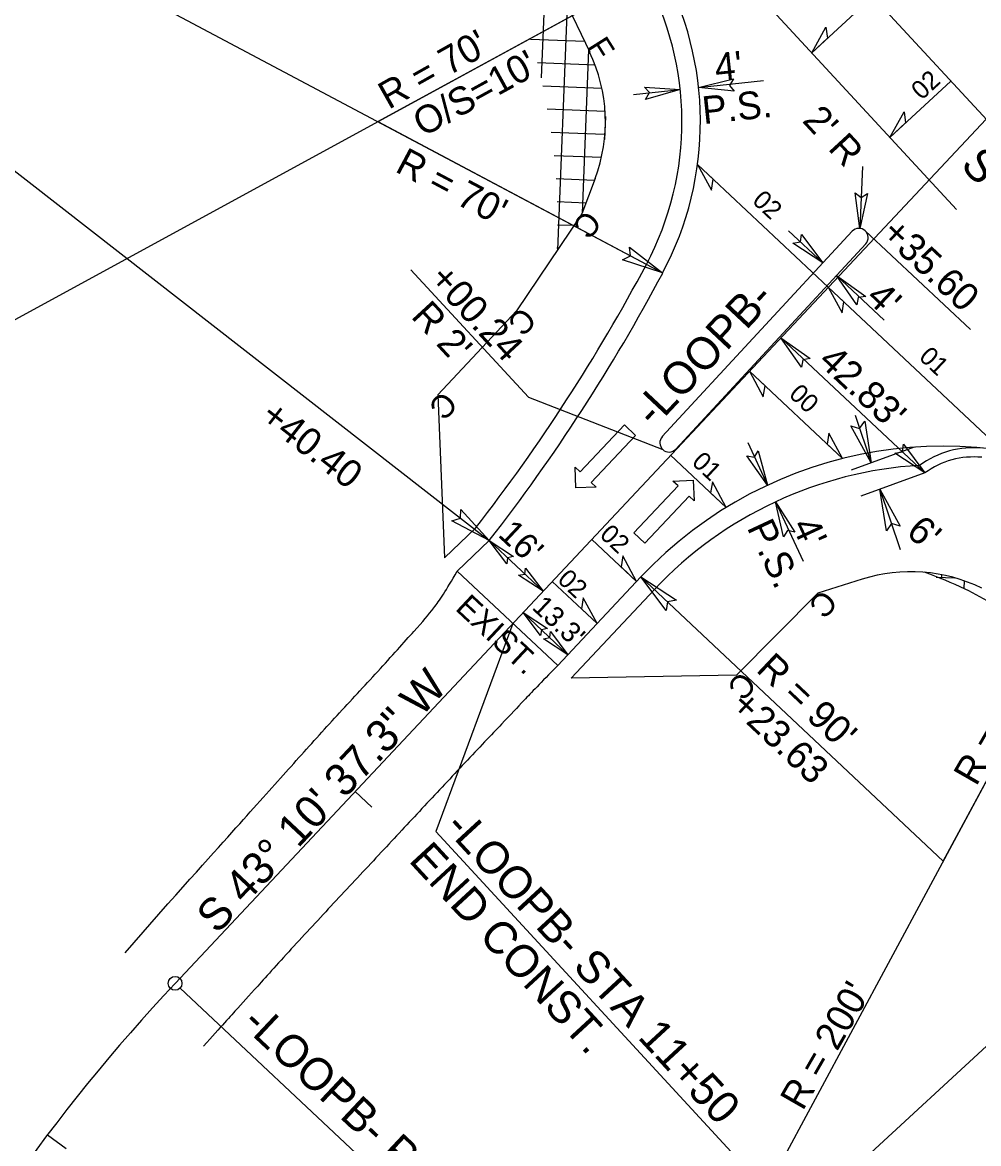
# Model space of a CAD drawing. Extents: x 1702862 to 1704514, y 793768 to 796215.
# Drawn here: x 1703124.4 to 1703331.8, y 795003.7 to 795246.9 of the extents above; entities that cross this region are included whole.
import ezdxf

# ---------------------------------------------------------------- set-up
doc = ezdxf.new("R2010")
doc.units = 0
for name, color, linetype in [('Old_Level_3', 7, 'Continuous'), ('Prop Conc 2ft 6in Curb and Gutter', 7, 'Continuous'), ('Prop Conc 5in Monolithic Surface Mount Island', 7, 'Continuous'), ('Prop Dimension', 7, 'Continuous'), ('Prop Dimension Text', 7, 'Continuous'), ('Prop DSN Text', 7, 'Continuous'), ('Prop EOT', 7, 'Continuous'), ('Prop Horizontal Alignment', 7, 'Continuous'), ('Prop Horizontal Alignment Direction Label', 7, 'Continuous'), ('Prop Horizontal Alignment Station Label', 7, 'Continuous'), ('Prop Horizontal Alignment Tick Small', 7, 'Continuous'), ('Prop Lane Arrow CELL', 7, 'Continuous'), ('Prop Lane Lines', 7, 'Continuous'), ('Prop Leader Line Medium', 7, 'Continuous'), ('Prop Paved Shoulder', 7, 'Continuous'), ('Prop Rem of Exist Asph Pvmt', 7, 'Continuous'), ('Prop SS Cut Line', 7, 'Continuous'), ('Prop SS Fill Line', 7, 'Continuous'), ('Prop SS Misc', 7, 'Continuous'), ('Prop SS Transition Line', 7, 'Continuous'), ('Prop Superelevation  Arrow CELL', 7, 'Continuous'), ('Prop Superelevation Label', 7, 'Continuous'), ('Prop Terminator CELL', 7, 'Continuous')]:
    doc.layers.add(name, color=color, linetype=linetype)

msp = doc.modelspace()

# ---------------------------------------------------------------- linework, layer by layer
at = {"layer": 'Old_Level_3'}
msp.add_line((1703146.71, 795045.13), (1703155.99, 795055.75), dxfattribs=at)
for points in [[(1703155.99, 795055.75), (1703165.31, 795066.15), (1703174.62, 795076.55), (1703183.93, 795086.95), (1703192.63, 795096.65), (1703201.54, 795106.13), (1703210.22, 795115.86), (1703213.5, 795119.53), (1703216.28, 795123.63), (1703218.73, 795127.89)], [(1703240.51, 795107.45), (1703236.69, 795103.55), (1703232.93, 795099.59), (1703229.18, 795095.63), (1703220.37, 795086.33), (1703211.61, 795076.99), (1703202.88, 795067.61), (1703193.66, 795057.72), (1703184.41, 795047.86), (1703175.36, 795037.82), (1703171.47, 795033.5), (1703167.57, 795029.18), (1703163.68, 795024.87)]]:
    msp.add_open_spline(points, degree=3, dxfattribs=at)
at = {"layer": 'Prop Conc 2ft 6in Curb and Gutter'}
msp.add_arc((1703330.77, 795134.69), 18, 84.5561, 126.0894, dxfattribs=at)
at = {"layer": 'Prop Conc 5in Monolithic Surface Mount Island'}
for p, q in [((1703304.39, 795201.63), (1703263.21, 795157.11)), ((1703304.39, 795201.63), (1703263.21, 795157.11)), ((1703266.15, 795154.39), (1703307.33, 795198.91)), ((1703266.15, 795154.39), (1703307.33, 795198.91))]:
    msp.add_line(p, q, dxfattribs=at)
for centre, start, end in [((1703305.86, 795200.27), 317.2317, 137.2317), ((1703305.86, 795200.27), 317.2317, 137.2317), ((1703264.68, 795155.75), 137.2317, 227.2317), ((1703264.68, 795155.75), 137.2317, 227.2317), ((1703264.68, 795155.75), 227.2317, 317.2317), ((1703264.68, 795155.75), 227.2317, 317.2317)]:
    msp.add_arc(centre, 2, start, end, dxfattribs=at)
at = {"layer": 'Prop Dimension'}
for p, q in [((1702910.07, 795380.31), (1703225.66, 795134.54)), ((1702910.07, 795380.31), (1703263.28, 795192.59)), ((1702911.8, 795067.36), (1703262.92, 795258.97)), ((1703201.47, 795225.44), (1703262.92, 795258.97)), ((1703271.07, 795232.84), (1703285.15, 795234.33)), ((1703256.95, 795231.34), (1703267.09, 795232.42)), ((1703201.47, 795225.44), (1703263.28, 795192.59)), ((1703306.63, 795215.67), (1703306.07, 795202.26)), ((1703290.61, 795201.75), (1703298.05, 795194.77)), ((1703330.07, 795180.3), (1703307.22, 795201.74)), ((1703300.96, 795192.03), (1703311.29, 795182.34)), ((1703288.93, 795178.54), (1703320.17, 795149.24)), ((1703305.02, 795161.75), (1703308.5, 795151.4)), ((1703281.72, 795155.79), (1703286.04, 795146.55)), ((1703317.84, 795154.78), (1703304.2, 795149.85)), ((1703272.02, 794968.13), (1703366.77, 795144.26)), ((1703310.41, 795145.71), (1703314.8, 795132.63)), ((1703324.13, 795065.01), (1703366.77, 795144.26)), ((1703287.73, 795142.92), (1703293.72, 795130.09)), ((1703237.35, 795123.57), (1703225.66, 795134.54)), ((1703324.13, 795065.01), (1703258.57, 795126.66)), ((1703258.57, 795126.66), (1703258.57, 795126.66)), ((1703233, 795118.93), (1703242.74, 795109.79)), ((1703272.02, 794968.13), (1703418.98, 795103.79))]:
    msp.add_line(p, q, dxfattribs=at)
msp.add_arc((1703324.13, 795065.01), 90, 136.7565, 136.7565, dxfattribs=at)
at = {"layer": 'Prop Dimension Text'}
msp.add_line((1703320.17, 795149.24), (1703306.25, 795144.2), dxfattribs=at)
msp.add_lwpolyline([(1703208.66, 795193.27), (1703234.17, 795165.64), (1703263.32, 795154.28)], dxfattribs=at)
at = {"layer": 'Prop EOT'}
for p, q in [((1703318.99, 795150.85), (1703320.17, 795149.24)), ((1703218.73, 795127.89), (1703225.66, 795134.54)), ((1703218.73, 795127.89), (1703240.51, 795107.45)), ((1703240.51, 795107.45), (1703258.57, 795126.66))]:
    msp.add_line(p, q, dxfattribs=at)
for centre, radius, start, end in [((1703201.47, 795225.44), 70, 332.0106, 28.6224), ((1702910.07, 795380.31), 400, 322.0902, 332.0106), ((1703324.13, 795065.01), 90, 61.7203, 136.7565), ((1703330.77, 795134.69), 20, 84.5561, 126.0894)]:
    msp.add_arc(centre, radius, start, end, dxfattribs=at)
at = {"layer": 'Prop Horizontal Alignment'}
for p, q in [((1703246.67, 795319.94), (1703723.92, 794802.92)), ((1703333.42, 795225.96), (1703157.53, 795038.5))]:
    msp.add_line(p, q, dxfattribs=at)
msp.add_arc((1703449.23, 794764.8), 400, 136.823, 153.353, dxfattribs=at)
at = {"layer": 'Prop Horizontal Alignment Station Label'}
msp.add_line((1703158.62, 795037.47), (1703250, 794951.74), dxfattribs=at)
msp.add_circle((1703157.53, 795038.5), 1.5, dxfattribs=at)
at = {"layer": 'Prop Horizontal Alignment Tick Small'}
for p, q in [((1703265, 795153.04), (1703268.65, 795149.61)), ((1703196.57, 795080.11), (1703200.22, 795076.69)), ((1703129.88, 795005.67), (1703133.88, 795002.66))]:
    msp.add_line(p, q, dxfattribs=at)
at = {"layer": 'Prop Lane Arrow CELL'}
for p, q in [((1703245.39, 795149.44), (1703254.99, 795159.62)), ((1703254.99, 795159.62), (1703257.39, 795157.36)), ((1703257.39, 795157.36), (1703247.79, 795147.17)), ((1703244.46, 795145.98), (1703244.29, 795150.46)), ((1703244.29, 795150.46), (1703245.39, 795149.44)), ((1703248.88, 795146.14), (1703244.46, 795145.98)), ((1703247.79, 795147.17), (1703248.88, 795146.14)), ((1703257.01, 795136.24), (1703266.61, 795146.43)), ((1703265.52, 795147.46), (1703269.93, 795147.62)), ((1703266.61, 795146.43), (1703265.52, 795147.46)), ((1703269.93, 795147.62), (1703270.1, 795143.14)), ((1703269.01, 795144.17), (1703259.41, 795133.98)), ((1703270.1, 795143.14), (1703269.01, 795144.17)), ((1703259.41, 795133.98), (1703257.01, 795136.24))]:
    msp.add_line(p, q, dxfattribs=at)
at = {"layer": 'Prop Lane Lines'}
msp.add_line((1703233.45, 795307.73), (1703326.99, 795206.39), dxfattribs=at)
at = {"layer": 'Prop Leader Line Medium'}
for p, q in [((1703230.79, 795116.57), (1703214.05, 795071.43)), ((1703214.05, 795071.43), (1703283.79, 794995.89))]:
    msp.add_line(p, q, dxfattribs=at)
at = {"layer": 'Prop Paved Shoulder'}
for p, q in [((1703215.96, 795130.77), (1703222.68, 795137.23)), ((1703243.42, 795104.71), (1703261.49, 795123.92))]:
    msp.add_line(p, q, dxfattribs=at)
for centre, radius, start, end in [((1703201.47, 795225.44), 66, 332.0106, 28.6224), ((1702910.07, 795380.31), 396, 322.1318, 332.0106), ((1703324.13, 795065.01), 86, 93.4265, 136.7565)]:
    msp.add_arc(centre, radius, start, end, dxfattribs=at)
at = {"layer": 'Prop Rem of Exist Asph Pvmt'}
for p, q in [((1703237.97, 795260.36), (1703236.95, 795234.91)), ((1703242.59, 795250.69), (1703240.46, 795197.58)), ((1703234.61, 795243.34), (1703246.32, 795242.87)), ((1703247.2, 795241.02), (1703245.79, 795205.57)), ((1703236.15, 795238.27), (1703248.61, 795237.77)), ((1703237.31, 795233.22), (1703250.1, 795232.71)), ((1703238.26, 795228.18), (1703250.79, 795227.68)), ((1703250.85, 795226.54), (1703250.64, 795221.53)), ((1703239.08, 795223.14), (1703250.69, 795222.68)), ((1703239.73, 795218.11), (1703250, 795217.7)), ((1703240.18, 795213.09), (1703248.49, 795212.76)), ((1703240.42, 795208.08), (1703246.64, 795207.83)), ((1703240.46, 795203.07), (1703244.06, 795202.93)), ((1703240.35, 795198.07), (1703240.78, 795198.06)), ((1703322.61, 795126.63), (1703326.65, 795126.47)), ((1703323.75, 795127.16), (1703323.71, 795126.17)), ((1703328.7, 795125.82), (1703328.63, 795124.13))]:
    msp.add_line(p, q, dxfattribs=at)
msp.add_spline([(1703351.72, 795107.76), (1703341.14, 795116.4), (1703328.87, 795124.03), (1703320.09, 795127.66)], degree=3, dxfattribs=at)
at = {"layer": 'Prop SS Cut Line'}
for p, q in [((1703245.72, 795205.41), (1703231.59, 795184.39)), ((1703231.59, 795184.39), (1703214.5, 795166.14)), ((1703306.56, 795126.16), (1703296.9, 795123.11)), ((1703296.9, 795123.11), (1703279.28, 795105.35))]:
    msp.add_line(p, q, dxfattribs=at)
at = {"layer": 'Prop SS Fill Line'}
msp.add_line((1703232.75, 795271.3), (1703247.45, 795240.51), dxfattribs=at)
at = {"layer": 'Prop SS Transition Line'}
for p, q in [((1703248.62, 795213.1), (1703245.72, 795205.41)), ((1703214.5, 795166.14), (1703215.96, 795130.77)), ((1703279.28, 795105.35), (1703243.42, 795104.71))]:
    msp.add_line(p, q, dxfattribs=at)
for centre, start, end in [((1703215.86, 795225.43), 339.3736, 25.5202), ((1703317.11, 795092.79), 63.9216, 107.5505)]:
    msp.add_arc(centre, 35, start, end, dxfattribs=at)
at = {"layer": 'Prop Superelevation  Arrow CELL'}
for p, q in [((1703308.85, 795252.58), (1703295.63, 795240.37)), ((1703325.81, 795234.21), (1703312.58, 795222)), ((1703270.85, 795216.11), (1703299.21, 795189.5)), ((1703299.21, 795189.5), (1703336.95, 795154.09)), ((1703282.11, 795171.27), (1703302.3, 795152.32)), ((1703265, 795153.04), (1703277.06, 795141.72)), ((1703247.89, 795134.8), (1703257.63, 795125.67)), ((1703239.34, 795125.69), (1703249.07, 795116.56))]:
    msp.add_line(p, q, dxfattribs=at)
for points in [[(1703295.63, 795240.37), (1703298.68, 795245.91), (1703299.02, 795243.51)], [(1703312.58, 795222), (1703315.63, 795227.54), (1703315.98, 795225.14)], [(1703270.85, 795216.11), (1703273.85, 795210.55), (1703274.22, 795212.95)], [(1703299.21, 795189.5), (1703302.22, 795183.93), (1703302.58, 795186.33)], [(1703282.11, 795171.27), (1703285.11, 795165.7), (1703285.48, 795168.1)], [(1703302.3, 795152.32), (1703299.29, 795157.88), (1703298.93, 795155.48)], [(1703277.06, 795141.72), (1703274.06, 795147.28), (1703273.69, 795144.88)], [(1703257.63, 795125.67), (1703254.63, 795131.23), (1703254.26, 795128.83)], [(1703249.07, 795116.56), (1703246.06, 795122.12), (1703245.7, 795119.72)]]:
    msp.add_lwpolyline(points, close=True, dxfattribs=at)
at = {"layer": 'Prop Terminator CELL'}
for points in [[(1703278.79, 795232.03), (1703271.07, 795232.84), (1703278.66, 795234.71), (1703277.77, 795233.28)], [(1703259.35, 795232.92), (1703267.09, 795232.42), (1703259.59, 795230.25), (1703260.42, 795231.71)], [(1703307.71, 795209.85), (1703306.07, 795202.26), (1703305.03, 795210), (1703306.35, 795208.97)], [(1703293.37, 795200.96), (1703298.05, 795194.77), (1703291.5, 795199.04), (1703293.15, 795199.36)], [(1703256.06, 795198.18), (1703263.28, 795192.59), (1703254.54, 795195.42), (1703256.31, 795196.29)], [(1703305.39, 795185.66), (1703300.96, 795192.03), (1703307.33, 795187.51), (1703305.67, 795187.25)], [(1703293.36, 795172.17), (1703288.93, 795178.54), (1703295.3, 795174.02), (1703293.65, 795173.76)], [(1703307.1, 795160.42), (1703308.5, 795151.4), (1703304.1, 795159.47), (1703305.98, 795158.89)], [(1703284, 795154.03), (1703286.04, 795146.55), (1703281.55, 795152.94), (1703283.2, 795152.63)], [(1703315.49, 795155.43), (1703320.17, 795149.24), (1703313.63, 795153.51), (1703315.27, 795153.83)], [(1703311.8, 795136.68), (1703310.41, 795145.71), (1703314.8, 795137.64), (1703312.92, 795138.22)], [(1703219.5, 795141.28), (1703225.66, 795134.54), (1703217.53, 795138.82), (1703219.42, 795139.38)], [(1703289.48, 795135.36), (1703287.73, 795142.92), (1703291.97, 795136.36), (1703290.33, 795136.73)], [(1703229.45, 795129.52), (1703225.66, 795134.54), (1703230.96, 795131.08), (1703229.63, 795130.82)], [(1703233.56, 795128.59), (1703237.35, 795123.57), (1703232.05, 795127.03), (1703233.39, 795127.29)], [(1703264.07, 795119.37), (1703258.57, 795126.66), (1703266.26, 795121.63), (1703264.33, 795121.25)], [(1703236.79, 795113.92), (1703233, 795118.93), (1703238.3, 795115.47), (1703236.97, 795115.21)], [(1703238.95, 795114.81), (1703242.74, 795109.79), (1703237.44, 795113.25), (1703238.78, 795113.52)]]:
    msp.add_lwpolyline(points, close=True, dxfattribs=at)

# ---------------------------------------------------------------- texts
at = {"layer": 'Prop Dimension'}
for s, height, rotation, p in [("O/S=10'", 6, 28.8804, (1703211.3, 795222)), ("4'", 6, 6.0681, (1703274.88, 795234.21)), ('P.S.', 6, 6.0681, (1703272.17, 795224.87)), ("2' R", 6, 312.7091, (1703293.37, 795225.51)), ('+35.60', 6, 316.823, (1703310.35, 795200.75)), ("4'", 6, 316.823, (1703307.13, 795186.9)), ("42.83'", 6, 316.823, (1703296.77, 795173.1)), ('P.S.', 6, 295.0403, (1703281.47, 795137.38)), ("4'", 6, 295.0403, (1703291.18, 795137.85)), ("16'", 5.4, 316.823, (1703227.34, 795135.62)), ("13.3'", 4.374, 316.823, (1703234.74, 795119.83))]:
    msp.add_text(s, height=height, rotation=rotation, dxfattribs=at).set_placement(p)
at = {"layer": 'Prop Dimension Text'}
for s, height, rotation, p in [("R = 70'", 6, 29.433, (1703203.85, 795227.96)), ("R = 70'", 6, 332.0106, (1703205, 795214.7)), ('+00.24', 6, 312.7091, (1703212.35, 795191.09)), ("R 2'", 6, 312.7091, (1703208.52, 795183.04)), ('+40.40', 6, 321.9909, (1703175.63, 795160.69)), ("6'", 6, 319.674, (1703315.83, 795135.94)), ('EXIST.', 5, 316.823, (1703218.09, 795119.64)), ("R = 90'", 6, 316.7565, (1703283.33, 795106.31)), ("R = 90'", 6, 60.1006, (1703331.27, 795081.07)), ('+23.63', 6, 316.7565, (1703277.71, 795098.3)), ("R = 200'", 6, 60.1006, (1703293.66, 795010.66))]:
    msp.add_text(s, height=height, rotation=rotation, dxfattribs=at).set_placement(p)
at = {"layer": 'Prop DSN Text'}
for s, p in [('-LOOPB- STA 11+50', (1703215.71, 795072.18)), ('END CONST.', (1703208, 795065.06))]:
    msp.add_text(s, height=7, rotation=312.7091, dxfattribs=at).set_placement(p)
at = {"layer": 'Prop Horizontal Alignment Direction Label'}
for s, rotation, p in [('S 42%%d 42\' 32.6" E', 312.7091, (1703327.66, 795215.83)), ('-LOOPB-', 46.823, (1703261.45, 795158.8)), ('S 43%%d 10\' 37.3" W', 46.823, (1703166.67, 795049))]:
    msp.add_text(s, height=7, rotation=rotation, dxfattribs=at).set_placement(p)
at = {"layer": 'Prop Horizontal Alignment Station Label'}
msp.add_text('-LOOPB- PC 12+57.06', height=7, rotation=316.823, dxfattribs=at).set_placement((1703171.76, 795029.45))
at = {"layer": 'Prop SS Misc'}
for s, rotation, p in [('F', 302.2972, (1703246.69, 795241.71)), ('C', 226.823, (1703246.77, 795206.53)), ('C', 226.823, (1703232.64, 795185.51)), ('C', 226.823, (1703215.55, 795167.26)), ('C', 226.823, (1703297.95, 795124.23)), ('C', 226.823, (1703280.34, 795106.47))]:
    msp.add_text(s, height=5, rotation=rotation, dxfattribs=at).set_placement(p)
at = {"layer": 'Prop Superelevation Label'}
for s, rotation, p in [('02', 42.7091, (1703319.46, 795229.94)), ('02', 316.823, (1703282.49, 795208)), ('01', 316.823, (1703318.64, 795174.09)), ('00', 316.823, (1703290.44, 795165.99)), ('01', 316.823, (1703269.37, 795151.29)), ('02', 316.823, (1703249.4, 795135.53)), ('02', 316.823, (1703240.24, 795125.8))]:
    msp.add_text(s, height=4, rotation=rotation, dxfattribs=at).set_placement(p)

doc.saveas('drawing.dxf')
